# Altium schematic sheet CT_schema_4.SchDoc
size 298 x 247 mm
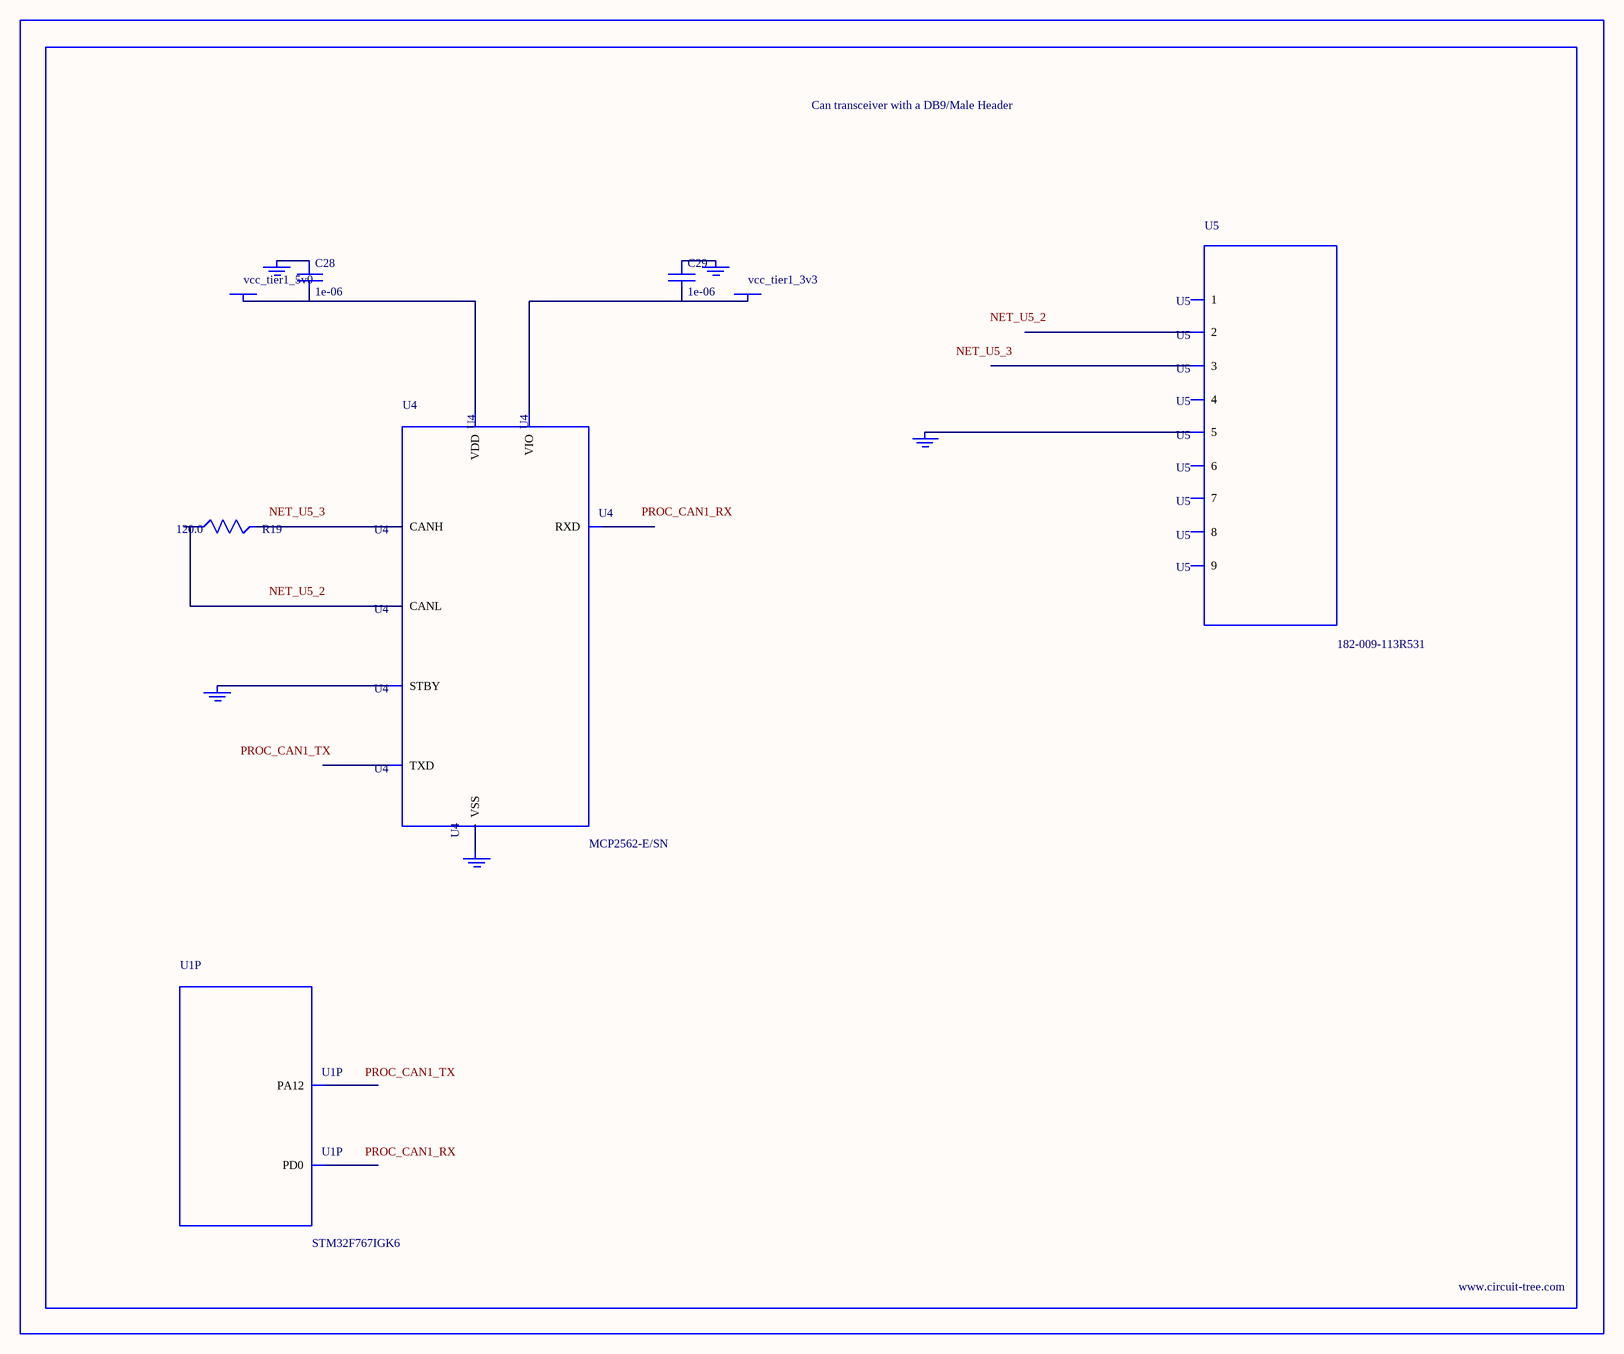
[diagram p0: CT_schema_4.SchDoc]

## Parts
BORDER3  (no value)
C28  1e-06  [C0603]
C29  1e-06  [C0603]
GND_INSTANCE_3_0  (no value)
GND_INSTANCE_3_1  (no value)
GND_INSTANCE_3_2  (no value)
GND_INSTANCE_3_3  (no value)
GND_INSTANCE_3_4  (no value)
POWER_INSTANCE_3_0  vcc_tier1_5v0
POWER_INSTANCE_3_1  vcc_tier1_3v3
R19  120.0  [R0603]
U1  STM32F767IGK6  [UFBGA176_25]  (part P of 16)
U4  MCP2562-E/SN  [SOIC-8]
U5  182-009-113R531  [182-009-MALE]

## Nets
NetC28_1: C28.1 GND_INSTANCE_3_0.0(GND)
NetC28_2: C28.2 POWER_INSTANCE_3_0.0(PWR) U4.3(VDD)
NetC29_1: C29.1 GND_INSTANCE_3_1.0(GND)
NetC29_2: C29.2 POWER_INSTANCE_3_1.0(PWR) U4.5(VIO)
NetGND_INSTANCE_3_2_0: GND_INSTANCE_3_2.0(GND) U4.8(STBY)
NetGND_INSTANCE_3_3_0: GND_INSTANCE_3_3.0(GND) U4.2(VSS)
NetGND_INSTANCE_3_4_0: GND_INSTANCE_3_4.0(GND) U5.5
NetR19_1: R19.1 U4.6(CANL)
NetR19_2: R19.2 U4.7(CANH)

Not connected (* = marked no-connect by the designer): U1 B12(PD0) B15(PA12); U4 1(TXD) 4(RXD); U5 1 2 3 4 6 7 8 9

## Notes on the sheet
- Labels drawn without touching a wire or pin: NET_U5_2, NET_U5_3, PROC_CAN1_RX, PROC_CAN1_TX

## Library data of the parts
BORDER3 = BORDER_PAGE3
C28 C29 = C0603C105K3RACTU
GND_INSTANCE_3_0-GND_INSTANCE_3_4 = GND
POWER_INSTANCE_3_0 POWER_INSTANCE_3_1 = PWR
R19 = RC0603JR-07120RL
